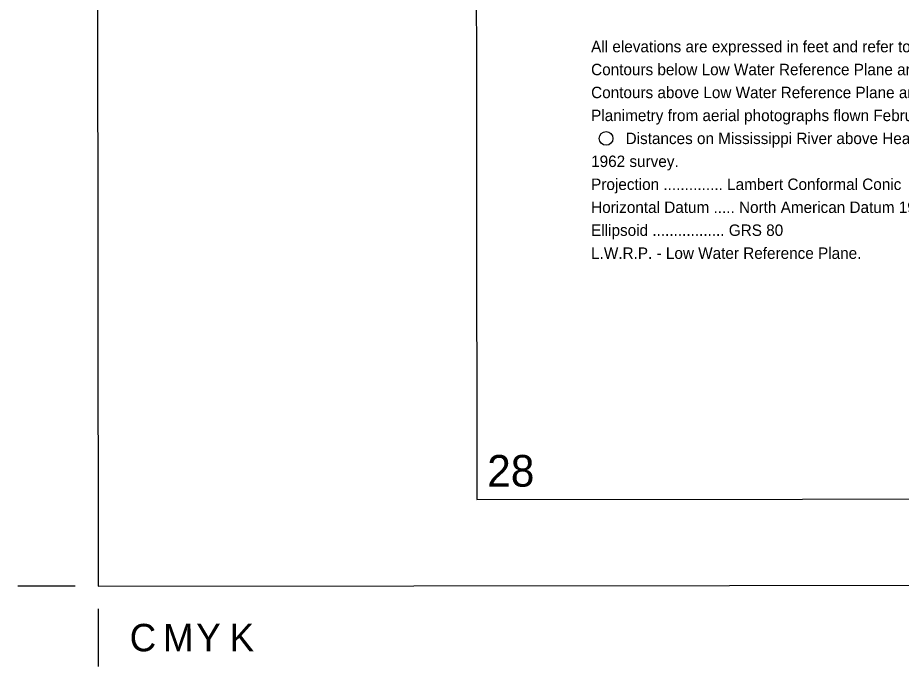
# Model space of a CAD drawing. Extents: x 3297753 to 3335611, y 652252 to 677623.
# Drawn here: x 3297778 to 3304191, y 652252 to 656962 of the extents above; entities that cross this region are included whole.
import ezdxf

# ---------------------------------------------------------------- set-up
doc = ezdxf.new("R2010")
doc.units = 0
for name, color, linetype in [('G-ANNO-NPLT', 7, 'Continuous'), ('V-ANNO-DIMS', 7, 'Continuous'), ('V-ANNO-NOTE', 7, 'Continuous'), ('V-ANNO-SYMB', 7, 'Continuous'), ('V-ANNO-TEXT', 7, 'Continuous')]:
    doc.layers.add(name, color=color, linetype=linetype)

msp = doc.modelspace()

# ---------------------------------------------------------------- linework, layer by layer
at = {"layer": 'G-ANNO-NPLT'}
msp.add_lwpolyline([(3298361, 652835.3), (3335027.7, 652872.7), (3335003.1, 677039.3), (3298336.4, 677002)], close=True, dxfattribs=at)
at = {"layer": 'V-ANNO-DIMS'}
for p, q in [((3298194.4, 652835.2), (3297777.7, 652834.8)), ((3298361.2, 652668.7), (3298361.6, 652252))]:
    msp.add_line(p, q, dxfattribs=at)
at = {"layer": 'V-ANNO-NOTE'}
msp.add_circle((3302048.1, 656085.8), 50, dxfattribs=at)
at = {"layer": 'V-ANNO-SYMB'}
msp.add_lwpolyline([(3301110.5, 653463.2), (3334193.7, 653496.9), (3334170.4, 676413.4), (3301087.2, 676379.8), (3301110.5, 653463.2)], dxfattribs=at)

# ---------------------------------------------------------------- texts
at = {"layer": 'V-ANNO-DIMS'}
for s, p in [('C', (3298590.5, 652360.9)), ('M', (3298832.1, 652361.2)), ('Y', (3299073.8, 652361.4)), ('K', (3299315.5, 652361.7))]:
    msp.add_text(s, height=199.3, rotation=0.0583, dxfattribs=at).set_placement(p)
at = {"layer": 'V-ANNO-NOTE'}
for s, rotation, p in [('All elevations are expressed in feet and refer to North American Vertical Datum of 1988.', 0.00001, (3301939.9, 656711.1)), ('Contours below Low Water Reference Plane are expressed in feet at 5 and 10 ft. intervals.', 0.00001, (3301939.9, 656544.4)), ('Contours above Low Water Reference Plane are expressed in feet at 5 ft. intervals.', 0.00001, (3301939.9, 656377.7)), ('Planimetry from aerial photographs flown February 2002.', 0.00001, (3301939.9, 656211)), ('Distances on Mississippi River above Head of Passes are shown at 1 mile intervals,', 0.00001, (3302190, 656044.3)), ('1962 survey.', 0.00001, (3301939.9, 655877.6)), ('Projection .............. Lambert Conformal Conic', 359.99998, (3301939.9, 655710.9)), ('Horizontal Datum ..... North American Datum 1983 (NAD 83)', 359.99998, (3301939.9, 655544.2)), ('Ellipsoid ................. GRS 80', 359.99998, (3301939.9, 655377.5)), ('L.W.R.P. - Low Water Reference Plane.', 359.99998, (3301939.9, 655210.8))]:
    msp.add_text(s, height=83, rotation=rotation, dxfattribs=at).set_placement(p)
at = {"layer": 'V-ANNO-TEXT'}
msp.add_text('28', height=230, rotation=0.0583, dxfattribs=at).set_placement((3301185.9, 653556.6))

doc.saveas('drawing.dxf')
